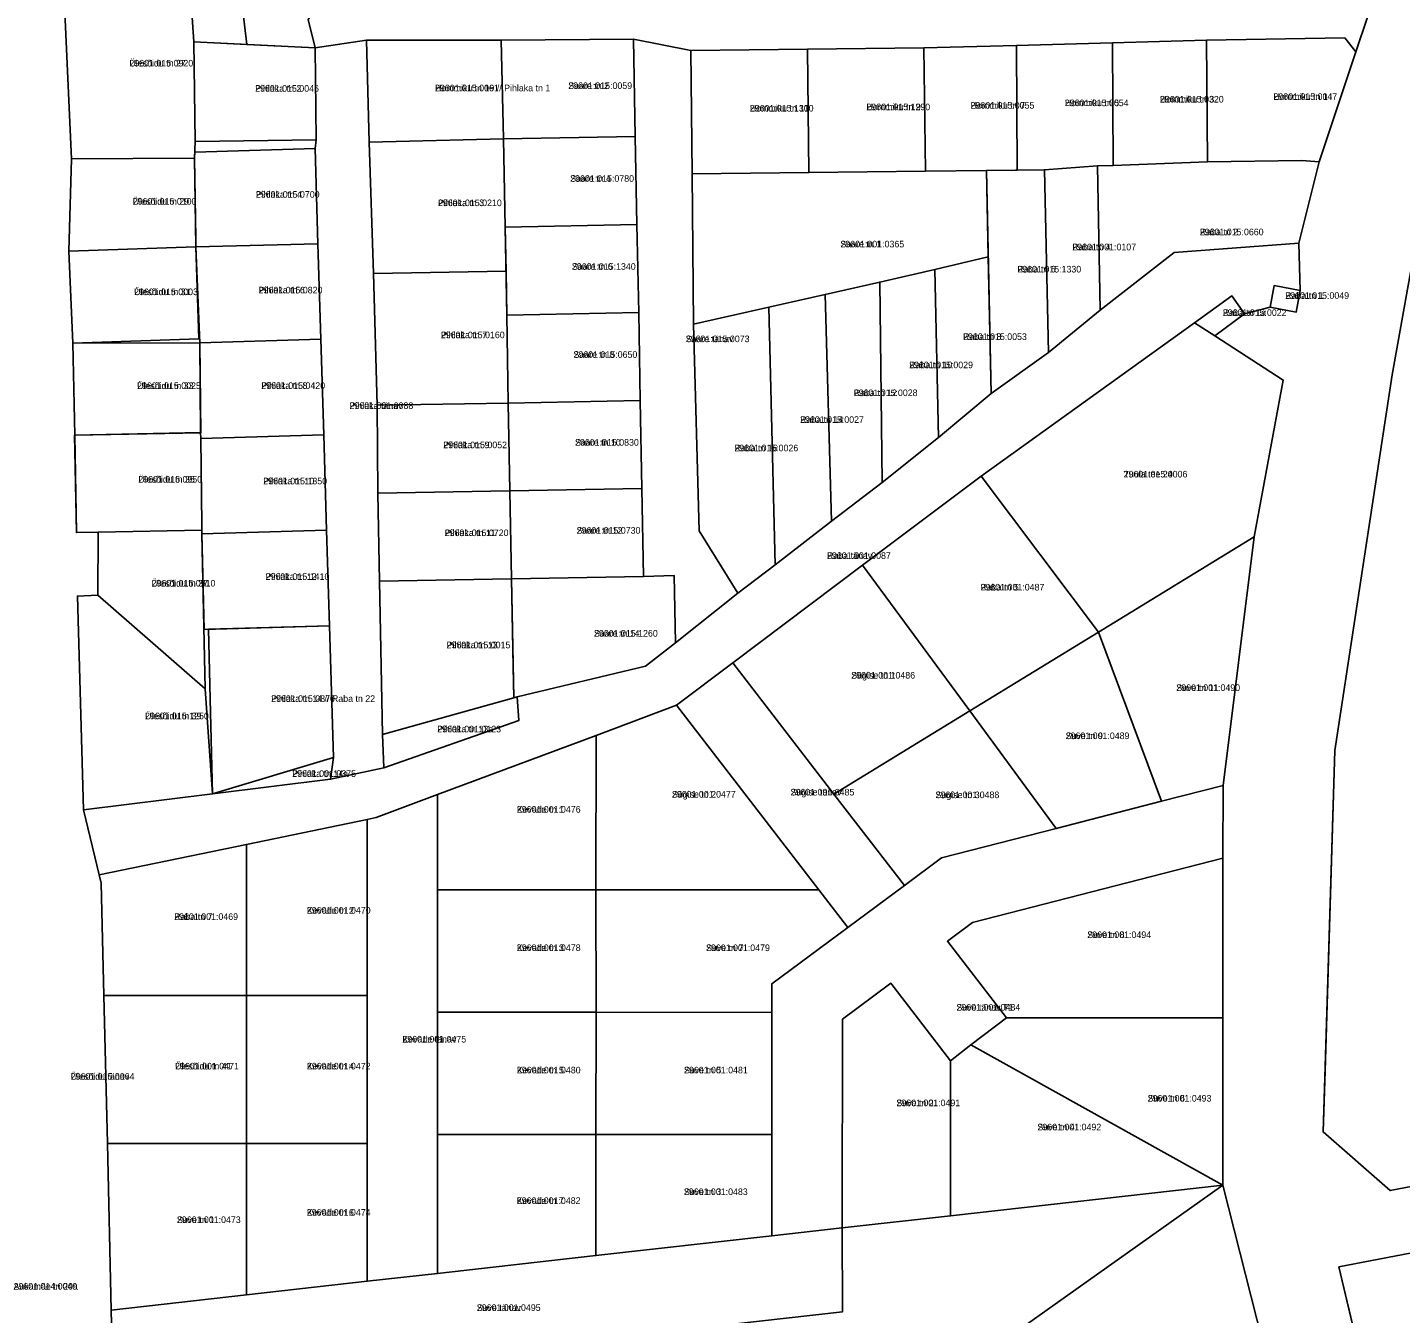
# Model space of a CAD drawing. Extents: x 518839 to 525192, y 6573164 to 6576561.
# Drawn here: x 524240.2 to 524552.3, y 6573574.3 to 6573866.6 of the extents above; entities that cross this region are included whole.
import ezdxf

# ---------------------------------------------------------------- set-up
doc = ezdxf.new("R2010")
doc.units = 0
for name, color, linetype in [('L_AADRESS', 7, 'Continuous'), ('PIIR', 7, 'Continuous'), ('TUNNUS', 7, 'Continuous')]:
    doc.layers.add(name, color=color, linetype=linetype)

msp = doc.modelspace()

# ---------------------------------------------------------------- linework, layer by layer
at = {"layer": 'PIIR'}
for points in [[(524731.67, 6574298.88), (524722.06, 6574288.12), (524718.22, 6574259.84), (524716.14, 6574215.55), (524706.65, 6574149.93), (524685.85, 6574091.49), (524672.92, 6574064.18), (524649.61, 6574022.41), (524618.73, 6573974.37), (524620.09, 6573959.72), (524619.11, 6573959.25), (524577.57, 6573939.19), (524550.39, 6573787.65), (524537.4, 6573702.27), (524534.73, 6573615.6), (524550, 6573602.27), (524580.86, 6573608.2), (524723.05, 6573635.5), (524732.83, 6573647.67)], [(524248.4, 6573876.78), (524250.25, 6573836.78), (524249.61, 6573815.83), (524250.51, 6573794.86), (524250.95, 6573773.98), (524251.33, 6573751.84), (524256.24, 6573751.93), (524256.23, 6573737.6), (524251.56, 6573737.38), (524252.91, 6573688.82), (524256.48, 6573674.06), (524256.96, 6573672.11), (524257.57, 6573646.62), (524258.38, 6573613), (524259.25, 6573575.13), (524259.66, 6573556.05), (524261.43, 6573479.78), (524278.19, 6573452.33), (524222.92, 6573446.04), (524240.81, 6573479.26), (524240.63, 6573494.16), (524239.93, 6573561.93)], [(524735.02, 6573622.76), (524723.6, 6573620.44), (524538.31, 6573584.92), (524550.61, 6573533.15), (524531.32, 6573527.03), (524511.92, 6573603.47), (524511.93, 6573641.51), (524511.96, 6573677.83), (524511.99, 6573694.36), (524519.02, 6573750.89), (524525.67, 6573786.48), (524510.13, 6573796.53), (524516.82, 6573801.58), (524522.7, 6573803.05), (524528.6, 6573801.93), (524529.53, 6573806.84), (524529.17, 6573817.64), (524533.84, 6573836.07), (524542.18, 6573861.09), (524547.46, 6573876.94)], [(524761.11, 6573457.07), (524598.59, 6573447.96), (524572.8, 6573488.89), (524550.61, 6573533.15), (524544.23, 6573560.02), (524538.31, 6573584.92), (524723.6, 6573620.44), (524735.02, 6573622.76)], [(524222.92, 6573446.04), (524278.19, 6573452.33), (524321.87, 6573468.64), (524511.92, 6573603.47), (524531.32, 6573527.03), (524518.18, 6573539.88), (524503.14, 6573549.18), (524475.23, 6573548.91), (524327.54, 6573432.69), (524232.37, 6573427.33)]]:
    msp.add_lwpolyline(points, dxfattribs=at)
for points in [[(524584.61, 6573702.16), (524580.86, 6573608.2), (524550, 6573602.27), (524534.73, 6573615.6), (524535.16, 6573629.46), (524537.4, 6573702.27), (524550.39, 6573787.65), (524577.57, 6573939.19), (524619.11, 6573959.25), (524620.09, 6573959.72), (524661.29, 6573960.53), (524645.64, 6573919.44), (524587.16, 6573765.94)], [(524303.34, 6573914.44), (524306.7, 6573883.35), (524307.7, 6573874.1), (524304.04, 6573868.46), (524305.58, 6573861.99), (524290.05, 6573862.75), (524284.19, 6573912.71)], [(524265.4, 6573910.2), (524284.19, 6573912.71), (524290.05, 6573862.75), (524278.05, 6573863.34), (524276.86, 6573880.16), (524268.86, 6573879.4)], [(524248.4, 6573876.78), (524268.86, 6573879.4), (524276.86, 6573880.16), (524278.05, 6573863.34), (524278.36, 6573840.72), (524278.14, 6573836.9), (524250.25, 6573836.78)], [(524307.7, 6573874.1), (524327.15, 6573873.14), (524348.36, 6573872.46), (524379.68, 6573874.03), (524409.34, 6573874.31), (524439.69, 6573875.03), (524469.67, 6573875.71), (524499.86, 6573876.34), (524539.01, 6573876.82), (524547.46, 6573876.94), (524542.18, 6573861.09), (524539.64, 6573864.28), (524508.18, 6573863.78), (524486.83, 6573863.15), (524465.01, 6573862.55), (524443.99, 6573861.97), (524417.49, 6573861.68), (524390.99, 6573861.38), (524377.97, 6573864.01), (524347.85, 6573863.73), (524317.26, 6573863.72), (524305.58, 6573861.99), (524304.04, 6573868.46)], [(524278.36, 6573840.72), (524278.05, 6573863.34), (524305.58, 6573861.99), (524305.86, 6573841.09)], [(524305.86, 6573841.09), (524305.58, 6573861.99), (524317.26, 6573863.72), (524317.86, 6573840.53), (524318.85, 6573810.75), (524319.66, 6573780.77), (524319.87, 6573760.76), (524320.24, 6573740.75), (524320.89, 6573705.95), (524321.24, 6573698.34), (524309.1, 6573695.78), (524309.78, 6573700.69), (524308.87, 6573730.67), (524308.21, 6573752.37), (524307.55, 6573774.06), (524306.89, 6573795.76), (524306.23, 6573817.45), (524305.58, 6573839.14)], [(524317.26, 6573863.72), (524347.85, 6573863.73), (524348.39, 6573841.31), (524317.86, 6573840.53)], [(524347.85, 6573863.73), (524377.97, 6573864.01), (524378.38, 6573841.87), (524348.39, 6573841.31)], [(524377.97, 6573864.01), (524390.99, 6573861.38), (524391.31, 6573833.38), (524391.61, 6573799.17), (524392.87, 6573752.21), (524401.7, 6573738.07), (524387.52, 6573726.75), (524387.22, 6573742.05), (524380.23, 6573741.86), (524379.85, 6573761.86), (524379.5, 6573781.86), (524379.14, 6573801.85), (524378.75, 6573821.87), (524378.38, 6573841.87)], [(524465.01, 6573862.55), (524486.83, 6573863.15), (524487, 6573835.27), (524483.47, 6573835.22), (524471.37, 6573834.28), (524465.18, 6573834.21)], [(524486.83, 6573863.15), (524508.18, 6573863.78), (524508.42, 6573836.13), (524487, 6573835.27)], [(524508.18, 6573863.78), (524539.64, 6573864.28), (524542.18, 6573861.09), (524533.84, 6573836.07), (524529.85, 6573836.39), (524508.42, 6573836.13)], [(524390.99, 6573861.38), (524417.49, 6573861.68), (524417.81, 6573833.68), (524391.31, 6573833.38)], [(524443.99, 6573861.97), (524444.31, 6573833.98), (524417.81, 6573833.68), (524417.49, 6573861.68)], [(524443.99, 6573861.97), (524465.01, 6573862.55), (524465.18, 6573834.21), (524458.17, 6573834.13), (524444.31, 6573833.98)], [(524317.86, 6573840.53), (524348.39, 6573841.31), (524348.79, 6573821.25), (524348.99, 6573811.26), (524318.85, 6573810.75)], [(524348.39, 6573841.31), (524378.38, 6573841.87), (524378.75, 6573821.87), (524348.79, 6573821.25)], [(524278.14, 6573836.9), (524278.22, 6573838.31), (524305.58, 6573839.14), (524306.23, 6573817.45), (524278.51, 6573816.74)], [(524278.14, 6573836.9), (524278.45, 6573818.67), (524278.51, 6573816.74), (524249.61, 6573815.83), (524250.25, 6573836.78)], [(524472.28, 6573792.73), (524471.37, 6573834.28), (524483.47, 6573835.22), (524484.06, 6573802.42)], [(524484.06, 6573802.42), (524483.47, 6573835.22), (524487, 6573835.27), (524508.42, 6573836.13), (524529.85, 6573836.39), (524533.84, 6573836.07), (524529.17, 6573817.64), (524500.83, 6573815.51)], [(524421.54, 6573805.94), (524408.73, 6573803.04), (524391.61, 6573799.17), (524391.31, 6573833.38), (524417.81, 6573833.68), (524444.31, 6573833.98), (524458.17, 6573834.13), (524458.6, 6573814.48), (524446.48, 6573811.59), (524433.94, 6573808.75)], [(524471.37, 6573834.28), (524472.28, 6573792.73), (524459.28, 6573783.45), (524458.17, 6573834.13)], [(524348.79, 6573821.25), (524378.75, 6573821.87), (524379.14, 6573801.85), (524349.16, 6573801.25)], [(524249.61, 6573815.83), (524278.51, 6573816.74), (524279.17, 6573795.87), (524250.51, 6573794.86)], [(524256.48, 6573674.06), (524252.91, 6573688.82), (524282.3, 6573692.46), (524309.1, 6573695.78), (524321.24, 6573698.34), (524351.9, 6573709.15), (524351.51, 6573714.5), (524380.71, 6573721.5), (524387.52, 6573726.75), (524401.7, 6573738.07), (524410.2, 6573744.5), (524422.95, 6573754.43), (524434.52, 6573763.24), (524447.32, 6573773.46), (524459.28, 6573783.45), (524472.28, 6573792.73), (524484.06, 6573802.42), (524500.83, 6573815.51), (524529.17, 6573817.64), (524529.53, 6573806.84), (524523.63, 6573807.96), (524522.7, 6573803.05), (524516.82, 6573801.58), (524513.98, 6573805.63), (524505.52, 6573799.52), (524457.01, 6573764.62), (524430.05, 6573744.4), (524400.54, 6573722.2), (524387.77, 6573712.57), (524369.46, 6573705.74), (524333.44, 6573692.3), (524319.44, 6573687.06), (524317.44, 6573686.65), (524289.99, 6573680.95)], [(524278.51, 6573816.74), (524306.23, 6573817.45), (524306.89, 6573795.76), (524279.41, 6573794.93)], [(524446.48, 6573811.59), (524458.6, 6573814.48), (524459.28, 6573783.45), (524447.32, 6573773.46)], [(524318.85, 6573810.75), (524348.99, 6573811.26), (524349.16, 6573801.25), (524349.5, 6573781.25), (524319.66, 6573780.77)], [(524433.94, 6573808.75), (524446.48, 6573811.59), (524447.32, 6573773.46), (524434.52, 6573763.24)], [(524421.54, 6573805.94), (524433.94, 6573808.75), (524434.52, 6573763.24), (524422.95, 6573754.43)], [(524523.63, 6573807.96), (524529.53, 6573806.84), (524528.6, 6573801.93), (524522.7, 6573803.05)], [(524421.54, 6573805.94), (524422.95, 6573754.43), (524410.2, 6573744.5), (524408.73, 6573803.04)], [(524516.82, 6573801.58), (524510.13, 6573796.53), (524505.52, 6573799.52), (524513.98, 6573805.63)], [(524349.16, 6573801.25), (524379.14, 6573801.85), (524379.5, 6573781.86), (524349.5, 6573781.25)], [(524391.61, 6573799.17), (524408.73, 6573803.04), (524410.2, 6573744.5), (524401.7, 6573738.07), (524392.87, 6573752.21)], [(524505.52, 6573799.52), (524510.13, 6573796.53), (524525.67, 6573786.48), (524519.02, 6573750.89), (524483.67, 6573729.2), (524457.01, 6573764.62)], [(524250.51, 6573794.86), (524279.41, 6573794.93), (524279.64, 6573774.53), (524250.95, 6573773.98)], [(524279.41, 6573794.93), (524306.89, 6573795.76), (524307.55, 6573774.06), (524279.59, 6573773.21), (524279.57, 6573774.54)], [(524349.5, 6573781.25), (524379.5, 6573781.86), (524379.85, 6573761.86), (524349.86, 6573761.31)], [(524319.66, 6573780.77), (524349.5, 6573781.25), (524349.86, 6573761.31), (524319.87, 6573760.76)], [(524250.88, 6573773.99), (524279.57, 6573774.54), (524279.59, 6573773.21), (524279.83, 6573753.6), (524279.84, 6573752.4), (524256.24, 6573751.93), (524251.33, 6573751.84)], [(524279.59, 6573773.21), (524307.55, 6573774.06), (524308.21, 6573752.37), (524279.86, 6573751.51), (524279.84, 6573752.4), (524279.83, 6573753.6)], [(524454.4, 6573711.32), (524430.05, 6573744.4), (524457.01, 6573764.62), (524483.67, 6573729.2)], [(524319.87, 6573760.76), (524349.86, 6573761.31), (524350.23, 6573741.31), (524320.24, 6573740.75)], [(524349.86, 6573761.31), (524379.85, 6573761.86), (524380.23, 6573741.86), (524350.23, 6573741.31)], [(524256.24, 6573751.93), (524279.84, 6573752.4), (524279.86, 6573751.51), (524280.63, 6573716.32), (524256.23, 6573737.6)], [(524279.86, 6573751.51), (524308.21, 6573752.37), (524308.87, 6573730.67), (524280.36, 6573729.78)], [(524498, 6573690.76), (524483.67, 6573729.2), (524519.02, 6573750.89), (524511.99, 6573694.36)], [(524423.51, 6573692.41), (524400.54, 6573722.2), (524430.05, 6573744.4), (524454.4, 6573711.32)], [(524320.24, 6573740.75), (524350.23, 6573741.31), (524350.6, 6573721.31), (524350.73, 6573714.3), (524320.89, 6573705.95)], [(524350.23, 6573741.31), (524380.23, 6573741.86), (524387.22, 6573742.05), (524387.52, 6573726.75), (524380.71, 6573721.5), (524351.51, 6573714.5), (524350.73, 6573714.3)], [(524256.23, 6573737.6), (524280.63, 6573716.32), (524282.3, 6573692.46), (524252.91, 6573688.82), (524251.56, 6573737.38)], [(524308.87, 6573730.67), (524309.78, 6573700.69), (524282.3, 6573692.46), (524281.72, 6573714.06), (524281.39, 6573729.84)], [(524474.06, 6573684.6), (524454.4, 6573711.32), (524483.67, 6573729.2), (524498, 6573690.76)], [(524420.12, 6573670.62), (524387.77, 6573712.57), (524400.54, 6573722.2), (524423.51, 6573692.41), (524439.56, 6573671.62), (524426.72, 6573662.08)], [(524321.24, 6573698.34), (524320.89, 6573705.95), (524350.73, 6573714.3), (524351.51, 6573714.5), (524351.9, 6573709.15)], [(524369.44, 6573670.63), (524369.46, 6573705.74), (524387.77, 6573712.57), (524420.12, 6573670.62)], [(524439.56, 6573671.62), (524423.51, 6573692.41), (524454.4, 6573711.32), (524474.06, 6573684.6), (524447.98, 6573677.88)], [(524333.44, 6573670.61), (524333.44, 6573692.3), (524369.46, 6573705.74), (524369.44, 6573670.63)], [(524282.3, 6573692.46), (524309.78, 6573700.69), (524309.1, 6573695.78)], [(524317.44, 6573646.64), (524317.44, 6573686.65), (524319.44, 6573687.06), (524333.44, 6573692.3), (524333.44, 6573670.61), (524333.44, 6573642.81), (524333.43, 6573615.02), (524333.44, 6573583.45), (524317.43, 6573581.67), (524317.43, 6573613)], [(524409.44, 6573642.78), (524409.44, 6573649.27), (524426.72, 6573662.08), (524439.56, 6573671.62), (524447.98, 6573677.88), (524474.06, 6573684.6), (524498, 6573690.76), (524511.99, 6573694.36), (524511.96, 6573677.83), (524455.02, 6573663.18), (524449.33, 6573658.95), (524462.74, 6573641.56), (524454.68, 6573635.38), (524450.04, 6573631.78), (524436.47, 6573649.41), (524425.44, 6573641.23), (524425.42, 6573593.78), (524409.43, 6573592), (524409.43, 6573615.02)], [(524289.98, 6573646.63), (524289.99, 6573680.95), (524317.44, 6573686.65), (524317.44, 6573646.64)], [(524256.96, 6573672.11), (524256.48, 6573674.06), (524289.99, 6573680.95), (524289.98, 6573646.63), (524257.57, 6573646.62)], [(524462.74, 6573641.56), (524449.33, 6573658.95), (524455.02, 6573663.18), (524511.96, 6573677.83), (524511.93, 6573641.51)], [(524333.44, 6573642.81), (524333.44, 6573670.61), (524369.44, 6573670.63), (524369.46, 6573642.81)], [(524369.46, 6573642.81), (524369.44, 6573670.63), (524420.12, 6573670.62), (524426.72, 6573662.08), (524409.44, 6573649.27), (524409.44, 6573642.78)], [(524425.42, 6573593.78), (524425.44, 6573641.23), (524436.47, 6573649.41), (524450.04, 6573631.78), (524450.05, 6573596.53)], [(524258.38, 6573613), (524257.57, 6573646.62), (524289.98, 6573646.63), (524289.96, 6573612.98)], [(524289.96, 6573612.98), (524289.98, 6573646.63), (524317.44, 6573646.64), (524317.43, 6573613)], [(524333.43, 6573615.02), (524333.44, 6573642.81), (524369.46, 6573642.81), (524369.44, 6573615.02)], [(524369.44, 6573615.02), (524369.46, 6573642.81), (524409.44, 6573642.78), (524409.43, 6573615.02)], [(524511.92, 6573603.47), (524454.68, 6573635.38), (524462.74, 6573641.56), (524511.93, 6573641.51)], [(524450.05, 6573596.53), (524450.04, 6573631.78), (524454.68, 6573635.38), (524511.92, 6573603.47)], [(524333.44, 6573583.45), (524333.43, 6573615.02), (524369.44, 6573615.02), (524369.43, 6573587.5)], [(524369.43, 6573587.5), (524369.44, 6573615.02), (524409.43, 6573615.02), (524409.43, 6573592)], [(524259.25, 6573575.13), (524258.38, 6573613), (524289.96, 6573612.98), (524289.97, 6573578.59)], [(524289.97, 6573578.59), (524289.96, 6573612.98), (524317.43, 6573613), (524317.43, 6573581.67)], [(524261.43, 6573479.78), (524259.66, 6573556.05), (524425.44, 6573574.71), (524425.42, 6573593.78), (524450.05, 6573596.53), (524511.92, 6573603.47), (524321.87, 6573468.64), (524278.19, 6573452.33)], [(524259.66, 6573556.05), (524259.25, 6573575.13), (524289.97, 6573578.59), (524317.43, 6573581.67), (524333.44, 6573583.45), (524369.43, 6573587.5), (524409.43, 6573592), (524425.42, 6573593.78), (524425.44, 6573574.71)]]:
    msp.add_lwpolyline(points, close=True, dxfattribs=at)

# ---------------------------------------------------------------- texts
at = {"layer": 'L_AADRESS'}
for s, p in [('Ülesõidu tn 27', (524263.38, 6573857.77)), ('Hommiku tn 19 // Pihlaka tn 1', (524332.84, 6573852.13)), ('Saare tn 2', (524363.15, 6573852.66)), ('Pihlaka tn 2', (524291.96, 6573852.03)), ('Hommiku tn 3', (524497.62, 6573849.58)), ('Hommiku tn 1', (524523.42, 6573850.18)), ('Hommiku tn 11', (524404.4, 6573847.53)), ('Hommiku tn 9', (524430.9, 6573847.83)), ('Hommiku tn 7', (524454.59, 6573848.18)), ('Hommiku tn 5', (524476, 6573848.75)), ('Saare tn 4', (524363.58, 6573831.56)), ('Pihlaka tn 4', (524292.11, 6573827.94)), ('Ülesõidu tn 29', (524264.13, 6573826.36)), ('Pihlaka tn 3', (524333.52, 6573826.03)), ('Raba tn 2', (524506.69, 6573819.41)), ('Saare tn 1', (524425, 6573816.65)), ('Raba tn 4', (524477.71, 6573815.99)), ('Saare tn 6', (524363.96, 6573811.56)), ('Raba tn 6', (524465.23, 6573810.95)), ('Ülesõidu tn 31', (524264.45, 6573805.8)), ('Pihlaka tn 6', (524292.76, 6573806.19)), ('Raba tn 1', (524526.12, 6573804.95)), ('Raba tn 1a', (524511.92, 6573801.08)), ('Pihlaka tn 7', (524334.18, 6573796.01)), ('Saare tänav', (524389.84, 6573795.11)), ('Raba tn 8', (524452.88, 6573795.61)), ('Saare tn 8', (524364.33, 6573791.55)), ('Raba tn 10', (524440.63, 6573789.19)), ('Ülesõidu tn 33', (524265.13, 6573784.46)), ('Pihlaka tn 8', (524293.36, 6573784.49)), ('Raba tn 12', (524428.03, 6573782.85)), ('Pihlaka tänav', (524313.41, 6573779.92)), ('Raba tn 14', (524415.84, 6573776.77)), ('Pihlaka tn 9', (524334.72, 6573771.01)), ('Saare tn 10', (524364.68, 6573771.58)), ('Raba tn 16', (524400.91, 6573770.31)), ('Ülesõidu tn 35', (524265.41, 6573763.19)), ('Pihlaka tn 10', (524293.81, 6573762.79)), ('Tuula tee 24', (524489.37, 6573764.36)), ('Pihlaka tn 11', (524335.05, 6573751.03)), ('Saare tn 12', (524365.04, 6573751.58)), ('Raba tänav', (524421.96, 6573745.85)), ('Ülesõidu tn 37', (524268.43, 6573739.57)), ('Pihlaka tn 12', (524294.33, 6573741.08)), ('Raba tn 5', (524456.86, 6573738.67)), ('Saare tn 14', (524368.98, 6573728.18)), ('Pihlaka tn 13', (524335.48, 6573725.53)), ('Sügise tn 1', (524427.47, 6573718.65)), ('Suve tn 11', (524501.35, 6573715.83)), ('Pihlaka tn 14 // Raba tn 22', (524295.59, 6573713.35)), ('Ülesõidu tn 39', (524266.93, 6573709.41)), ('Pihlaka tn 13a', (524333.36, 6573706.42)), ('Suve tn 9', (524476.2, 6573704.89)), ('Pihlaka tn 14a', (524300.39, 6573696.31)), ('Sügise tn 2', (524386.7, 6573691.6)), ('Sügise tänav', (524413.67, 6573692.08)), ('Sügise tn 3', (524446.62, 6573691.47)), ('Kevade tn 1', (524351.44, 6573688.17)), ('Kevade tn 2', (524303.71, 6573665.22)), ('Raba tn 7', (524273.57, 6573663.79)), ('Suve tn 8', (524481.12, 6573659.67)), ('Kevade tn 3', (524351.44, 6573656.72)), ('Suve tn 7', (524394.46, 6573656.71)), ('Suve tänav T1', (524451.38, 6573643.18)), ('Kevade tänav', (524325.43, 6573635.93)), ('Ülesõidu tänav', (524250.04, 6573627.47)), ('Ülesõidu tn 41', (524273.77, 6573629.81)), ('Kevade tn 4', (524303.7, 6573629.81)), ('Kevade tn 5', (524351.44, 6573628.91)), ('Suve tn 5', (524389.44, 6573628.91)), ('Suve tn 2', (524437.73, 6573621.46)), ('Suve tn 6', (524494.84, 6573622.51)), ('Suve tn 4', (524469.78, 6573615.96)), ('Suve tn 3', (524389.43, 6573601.26)), ('Kevade tn 6', (524303.7, 6573596.56)), ('Kevade tn 7', (524351.43, 6573599.24)), ('Suve tn 1', (524274.18, 6573594.9)), ('Aukamäe tn 20a', (524237.05, 6573579.76)), ('Suve tänav', (524342.35, 6573574.92))]:
    msp.add_text(s, height=1.5, dxfattribs=at).set_placement(p)
at = {"layer": 'TUNNUS'}
for s, p in [('29601:015:0920', (524263.38, 6573857.77)), ('29601:015:0061', (524332.84, 6573852.13)), ('29601:015:0059', (524363.15, 6573852.66)), ('29601:015:0046', (524291.96, 6573852.03)), ('29601:015:0320', (524497.62, 6573849.58)), ('29601:015:0047', (524523.42, 6573850.18)), ('29601:015:1300', (524404.4, 6573847.53)), ('29601:015:1290', (524430.9, 6573847.83)), ('29601:015:0055', (524454.59, 6573848.18)), ('29601:015:0054', (524476, 6573848.75)), ('29601:015:0780', (524363.58, 6573831.56)), ('29601:015:0700', (524292.11, 6573827.94)), ('29601:015:0100', (524264.13, 6573826.36)), ('29601:015:0210', (524333.52, 6573826.03)), ('29601:015:0660', (524506.69, 6573819.41)), ('29601:001:0365', (524425, 6573816.65)), ('29601:001:0107', (524477.71, 6573815.99)), ('29601:015:1340', (524363.96, 6573811.56)), ('29601:015:1330', (524465.23, 6573810.95)), ('29601:015:0003', (524264.45, 6573805.8)), ('29601:015:0820', (524292.76, 6573806.19)), ('29601:015:0049', (524526.12, 6573804.95)), ('29601:015:0022', (524511.92, 6573801.08)), ('29601:015:0160', (524334.18, 6573796.01)), ('29601:015:0073', (524389.84, 6573795.11)), ('29601:015:0053', (524452.88, 6573795.61)), ('29601:015:0650', (524364.33, 6573791.55)), ('29601:015:0029', (524440.63, 6573789.19)), ('29601:015:0025', (524265.13, 6573784.46)), ('29601:015:0420', (524293.36, 6573784.49)), ('29601:015:0028', (524428.03, 6573782.85)), ('29601:001:0088', (524313.41, 6573779.92)), ('29601:015:0027', (524415.84, 6573776.77)), ('29601:015:0052', (524334.72, 6573771.01)), ('29601:015:0830', (524364.68, 6573771.58)), ('29601:015:0026', (524400.91, 6573770.31)), ('29601:015:0950', (524265.41, 6573763.19)), ('29601:015:1350', (524293.81, 6573762.79)), ('29601:015:0006', (524489.37, 6573764.36)), ('29601:015:0720', (524335.05, 6573751.03)), ('29601:015:0730', (524365.04, 6573751.58)), ('29601:001:0087', (524421.96, 6573745.85)), ('29601:015:1410', (524294.33, 6573741.08)), ('29601:015:0910', (524268.43, 6573739.57)), ('29601:001:0487', (524456.86, 6573738.67)), ('29601:015:1260', (524368.98, 6573728.18)), ('29601:015:0015', (524335.48, 6573725.53)), ('29601:001:0486', (524427.47, 6573718.65)), ('29601:001:0490', (524501.35, 6573715.83)), ('29601:015:0870', (524295.59, 6573713.35)), ('29601:015:1250', (524266.93, 6573709.41)), ('29601:001:0123', (524333.36, 6573706.42)), ('29601:001:0489', (524476.2, 6573704.89)), ('29601:001:0375', (524300.39, 6573696.31)), ('29601:001:0477', (524386.7, 6573691.6)), ('29601:001:0485', (524413.67, 6573692.08)), ('29601:001:0488', (524446.62, 6573691.47)), ('29601:001:0476', (524351.44, 6573688.17)), ('29601:001:0470', (524303.71, 6573665.22)), ('29601:001:0469', (524273.57, 6573663.79)), ('29601:001:0494', (524481.12, 6573659.67)), ('29601:001:0478', (524351.44, 6573656.72)), ('29601:001:0479', (524394.46, 6573656.71)), ('29601:001:0484', (524451.38, 6573643.18)), ('29601:001:0475', (524325.43, 6573635.93)), ('29601:015:0064', (524250.04, 6573627.47)), ('29601:001:0471', (524273.77, 6573629.81)), ('29601:001:0472', (524303.7, 6573629.81)), ('29601:001:0480', (524351.44, 6573628.91)), ('29601:001:0481', (524389.44, 6573628.91)), ('29601:001:0491', (524437.73, 6573621.46)), ('29601:001:0493', (524494.84, 6573622.51)), ('29601:001:0492', (524469.78, 6573615.96)), ('29601:001:0483', (524389.43, 6573601.26)), ('29601:001:0474', (524303.7, 6573596.56)), ('29601:001:0482', (524351.43, 6573599.24)), ('29601:001:0473', (524274.18, 6573594.9)), ('29601:014:0049', (524237.05, 6573579.76)), ('29601:001:0495', (524342.35, 6573574.92))]:
    msp.add_text(s, height=1.5, dxfattribs=at).set_placement(p)

doc.saveas('drawing.dxf')
